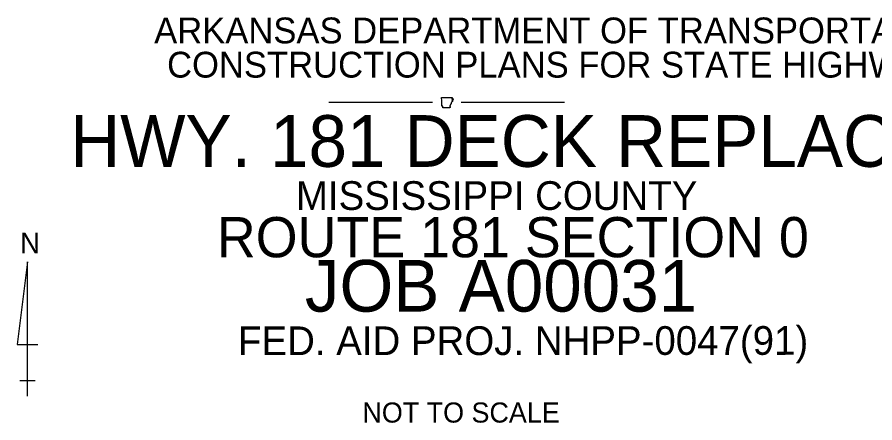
# Model space of a CAD drawing. Extents: x 2520745 to 2582119, y -1491628 to -1461664.
# Drawn here: x 2533060 to 2555441, y -1472350 to -1461753 of the extents above; entities that cross this region are included whole.
import ezdxf

# ---------------------------------------------------------------- set-up
doc = ezdxf.new("R2010")
doc.units = 0
doc.layers.add('2', color=7, linetype='Continuous')
doc.layers.add('R_Draft', color=7, linetype='Continuous')

msp = doc.modelspace()

# ---------------------------------------------------------------- linework, layer by layer
at = {"layer": 'R_Draft'}
for p, q in [((2541196.5562201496, -1463975.9826834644), (2543896.5562205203, -1463975.9826834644)), ((2544646.5562201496, -1463975.9826834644), (2547346.5562205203, -1463975.9826834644)), ((2533329.603670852, -1468144.847094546), (2533059.603670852, -1470304.847094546)), ((2533329.603670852, -1471654.8470944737), (2533329.603670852, -1468144.847094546)), ((2533059.603670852, -1470304.847094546), (2533599.603670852, -1470304.847094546)), ((2533125.853670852, -1471244.8470944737), (2533530.853670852, -1471244.8470944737))]:
    msp.add_line(p, q, dxfattribs=at)
for points in [[(2544131.813700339, -1463851.2283421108), (2544213.6743253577, -1463851.2789671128), (2544285.5112003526, -1463851.1270921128), (2544370.2574503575, -1463849.8108421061), (2544409.5424503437, -1463848.8995921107)], [(2544137.7368253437, -1464072.7127171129), (2544142.2930753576, -1463935.3670921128), (2544131.813700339, -1463851.2283421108)], [(2544397.3924503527, -1463888.4377171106), (2544435.8168253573, -1463886.4633421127)], [(2544351.374325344, -1464122.1227171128), (2544165.8337003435, -1464121.8189671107), (2544165.7324503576, -1464080.8633421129)]]:
    msp.add_lwpolyline(points, dxfattribs=at)
for points in [[(2544394.0005753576, -1463985.3845921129), (2544392.8362003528, -1463986.8527171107), (2544391.1149503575, -1463985.9414671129), (2544391.1149503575, -1463984.7264671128), (2544391.3680753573, -1463983.460842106), (2544390.7605753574, -1463982.6508421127), (2544389.6974503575, -1463983.0052171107), (2544389.6974503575, -1463984.5745921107), (2544389.5962003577, -1463986.0933421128), (2544389.2924503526, -1463988.2702171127), (2544390.001200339, -1463988.9283421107), (2544391.6212003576, -1463989.1308421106), (2544392.785575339, -1463989.4345921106), (2544393.4943253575, -1463990.5989671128), (2544393.4437003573, -1463992.0164671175), (2544392.8868253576, -1463993.3833421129), (2544392.0768253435, -1463994.497092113), (2544390.811200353, -1463994.9020921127), (2544389.7987003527, -1463994.2439671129), (2544389.393700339, -1463992.9277171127), (2544388.9380753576, -1463991.7633421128), (2544388.077450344, -1463990.9027171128), (2544387.1662003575, -1463991.8645921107), (2544386.9637003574, -1463993.6364671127), (2544387.0143253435, -1463995.1552171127), (2544387.0143253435, -1463997.2308421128), (2544388.3305753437, -1463998.5977171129), (2544389.140575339, -1464000.1670921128), (2544388.887450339, -1464001.5845921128), (2544387.925575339, -1464003.2552171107), (2544387.5205753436, -1464004.7233421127), (2544387.1155753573, -1464006.6977171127), (2544387.1662003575, -1464008.8745921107), (2544386.811825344, -1464011.0008421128), (2544386.103075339, -1464012.4183421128), (2544384.7868253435, -1464013.5827171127), (2544383.926200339, -1464014.3420921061), (2544383.217450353, -1464015.1014671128), (2544382.863075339, -1464016.620217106), (2544382.609950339, -1464017.6833421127), (2544381.6480753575, -1464018.9489671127), (2544380.888700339, -1464019.0502171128), (2544380.281200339, -1464018.5439671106), (2544380.0787003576, -1464017.6833421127), (2544380.0787003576, -1464016.8227171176), (2544379.6737003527, -1464015.9620921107), (2544378.408075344, -1464015.6077171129), (2544377.3955753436, -1464015.6583421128), (2544376.9399503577, -1464016.3670921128), (2544377.5980753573, -1464018.3414671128), (2544377.8512003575, -1464019.6070921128), (2544377.496825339, -1464021.3283421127), (2544377.6993253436, -1464021.5308421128), (2544375.876825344, -1464022.4927171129), (2544374.4087003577, -1464022.6445921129), (2544373.1937003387, -1464022.9989671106), (2544372.029325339, -1464023.7583421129), (2544371.4724503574, -1464024.8720921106), (2544370.6624503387, -1464025.7833421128), (2544369.953700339, -1464026.6439671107), (2544368.9918253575, -1464027.0489671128), (2544367.9287003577, -1464026.8464671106), (2544366.5112003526, -1464026.694592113), (2544365.701200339, -1464027.7070921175), (2544365.954325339, -1464029.1752171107), (2544366.9162003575, -1464030.0358421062), (2544368.3337003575, -1464030.4408421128), (2544369.8018253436, -1464030.3395921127), (2544371.2193253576, -1464030.1877171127), (2544372.5355753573, -1464030.8964671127), (2544372.282450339, -1464032.2633421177), (2544371.0168253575, -1464032.9214671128), (2544369.1437003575, -1464033.1239671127), (2544367.6249503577, -1464032.9720921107), (2544365.8024503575, -1464033.3770921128), (2544364.891200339, -1464034.5414671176), (2544365.397450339, -1464036.3133421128), (2544367.3718253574, -1464037.0220921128), (2544368.283075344, -1464038.6927171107), (2544368.3337003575, -1464040.2620921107), (2544367.6755753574, -1464042.3377171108), (2544366.7643253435, -1464043.2995921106), (2544364.9924503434, -1464043.7045921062), (2544363.625575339, -1464043.9577171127), (2544363.423075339, -1464046.2864671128), (2544362.815575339, -1464047.4508421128), (2544361.7524503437, -1464047.8052171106), (2544360.233700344, -1464047.0458421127), (2544359.3224503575, -1464046.6914671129), (2544358.2087003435, -1464046.1852171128), (2544356.791200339, -1464045.3245921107), (2544355.7280753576, -1464045.476467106), (2544356.031825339, -1464047.7039671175), (2544356.1330753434, -1464047.8052171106), (2544357.348075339, -1464049.475842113), (2544358.5630753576, -1464050.7920921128), (2544359.1199503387, -1464052.3614671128)], [(2544415.971825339, -1463935.2152171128), (2544416.1743253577, -1463936.6833421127), (2544415.3137003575, -1463938.2527171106), (2544415.009950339, -1463939.8220921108), (2544415.1618253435, -1463941.3914671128), (2544413.5418253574, -1463942.2520921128), (2544412.1243253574, -1463943.2645921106), (2544412.934325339, -1463944.4795921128), (2544414.4530753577, -1463945.5933421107), (2544415.971825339, -1463946.4539671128), (2544416.9337003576, -1463947.3145921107), (2544417.1868253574, -1463949.3902171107), (2544417.4399503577, -1463950.7064671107), (2544417.9462003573, -1463952.5289671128), (2544418.1487003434, -1463953.7945921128), (2544417.237450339, -1463955.3133421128), (2544416.1743253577, -1463955.6170921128), (2544415.0605753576, -1463955.2627171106), (2544413.7443253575, -1463955.1614671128), (2544412.681200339, -1463956.1739671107), (2544411.9218253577, -1463957.5914671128), (2544411.1624503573, -1463959.0089671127), (2544410.6055753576, -1463960.2239671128), (2544410.0487003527, -1463961.5402171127), (2544408.9349503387, -1463963.0589671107), (2544407.5680753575, -1463963.3120921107), (2544405.9480753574, -1463963.7170921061), (2544404.986200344, -1463964.8308421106), (2544405.1380753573, -1463966.7039671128), (2544406.0493253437, -1463967.9695921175), (2544406.7580753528, -1463969.5389671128), (2544407.264325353, -1463970.9058421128), (2544407.0112003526, -1463972.6270921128), (2544406.3024503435, -1463973.8927171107), (2544405.391200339, -1463974.6520921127), (2544404.986200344, -1463976.2720921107), (2544404.328075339, -1463977.487092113), (2544403.720575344, -1463977.892092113), (2544402.5055753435, -1463977.7908421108), (2544401.1893253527, -1463977.5377171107), (2544400.0755753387, -1463977.6389671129), (2544399.012450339, -1463978.1958421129), (2544397.9493253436, -1463977.8414671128), (2544396.8355753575, -1463976.6264671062), (2544395.9243253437, -1463975.7152171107), (2544394.9118253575, -1463975.360842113), (2544393.8487003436, -1463975.9177171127), (2544393.6462003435, -1463977.5883421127), (2544394.1524503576, -1463979.309592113), (2544394.6080753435, -1463981.6383421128), (2544394.1524503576, -1463983.0558421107), (2544394.0005753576, -1463985.3845921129)], [(2544409.5424503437, -1463848.8995921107), (2544409.7955753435, -1463851.1270921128), (2544410.504325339, -1463852.2914671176), (2544410.6055753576, -1463854.4177171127), (2544411.4662003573, -1463855.3289671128), (2544412.934325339, -1463856.2402171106), (2544414.2505753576, -1463857.7083421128), (2544414.5543253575, -1463859.4295921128), (2544414.149325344, -1463861.2014671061), (2544414.0480753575, -1463863.1758421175), (2544413.845575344, -1463864.8970921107), (2544413.5418253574, -1463866.4664671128), (2544412.3268253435, -1463867.7320921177), (2544411.1624503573, -1463868.643342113), (2544410.0993253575, -1463869.7064671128), (2544409.3399503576, -1463870.8202171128), (2544408.0237003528, -1463872.0352171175), (2544406.7074503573, -1463873.3008421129), (2544405.644325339, -1463874.4145921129), (2544404.5812003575, -1463875.8320921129), (2544404.074950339, -1463877.4014671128), (2544402.910575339, -1463878.5152171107), (2544401.999325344, -1463879.5277171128), (2544400.7843253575, -1463880.8945921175), (2544400.1768253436, -1463882.2614671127), (2544399.012450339, -1463883.830842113), (2544398.759325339, -1463885.3495921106), (2544397.999950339, -1463886.5645921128), (2544397.9493253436, -1463886.767092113)], [(2544435.259950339, -1463886.5139671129), (2544435.8168253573, -1463886.4633421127), (2544437.5380753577, -1463888.2858421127), (2544438.2974503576, -1463889.804592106), (2544439.4112003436, -1463890.6652171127), (2544440.6768253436, -1463891.1208421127), (2544441.6387003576, -1463892.2852171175), (2544442.296825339, -1463893.5508421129), (2544441.942450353, -1463894.6645921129), (2544440.5249503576, -1463894.7658421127), (2544438.9555753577, -1463895.0189671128), (2544437.436825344, -1463894.9683421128), (2544436.2218253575, -1463895.9808421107), (2544437.335575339, -1463897.3477171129), (2544438.8037003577, -1463898.6133421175), (2544439.2087003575, -1463899.9802171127), (2544438.3987003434, -1463901.2964671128), (2544436.7787003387, -1463902.0052171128), (2544435.2093253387, -1463902.6127171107), (2544433.7918253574, -1463903.8277171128), (2544433.133700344, -1463904.9920921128), (2544431.564325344, -1463905.4983421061), (2544429.9443253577, -1463905.9539671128), (2544428.5268253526, -1463906.1058421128), (2544426.906825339, -1463906.4095921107), (2544425.337450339, -1463907.1689671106), (2544424.6793253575, -1463908.4852171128), (2544424.8818253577, -1463910.3583421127), (2544424.831200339, -1463912.3327171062), (2544426.5018253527, -1463912.9908421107), (2544427.969950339, -1463913.0414671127), (2544429.3874503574, -1463913.8008421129), (2544429.235575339, -1463914.9145921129), (2544428.172450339, -1463916.3320921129), (2544426.906825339, -1463917.4458421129), (2544425.641200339, -1463918.0027171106), (2544424.4768253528, -1463919.0658421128), (2544424.8818253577, -1463920.1289671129), (2544425.9449503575, -1463920.8377171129), (2544426.7043253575, -1463922.0020921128), (2544426.603075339, -1463923.0652171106), (2544425.3880753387, -1463923.8245921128), (2544424.071825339, -1463923.5208421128), (2544423.1099503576, -1463922.2552171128), (2544421.9962003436, -1463921.8502171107), (2544421.0343253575, -1463921.3945921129), (2544419.920575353, -1463922.0527171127), (2544419.920575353, -1463923.5208421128), (2544419.5155753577, -1463925.0902171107), (2544419.8699503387, -1463926.2545921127), (2544420.3255753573, -1463927.8745921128), (2544420.2749503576, -1463929.0895921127), (2544419.8699503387, -1463930.8108421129), (2544419.0093253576, -1463932.5827171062), (2544417.9968253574, -1463933.1395921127), (2544417.5918253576, -1463931.2158421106), (2544417.389325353, -1463929.6464671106), (2544416.781825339, -1463928.7352171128), (2544415.971825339, -1463928.6845921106), (2544414.9087003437, -1463929.4439671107), (2544413.7443253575, -1463930.6083421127), (2544412.2762003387, -1463931.8739671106), (2544411.4155753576, -1463933.1395921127), (2544411.8712003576, -1463934.7089671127), (2544412.9849503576, -1463935.1139671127), (2544413.845575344, -1463934.8102171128), (2544414.3012003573, -1463933.7977171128), (2544415.1618253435, -1463933.6458421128), (2544415.971825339, -1463935.2152171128)], [(2544165.7324503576, -1464080.8633421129), (2544165.9349503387, -1464080.9645921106), (2544164.9730753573, -1464080.3064671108), (2544163.6568253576, -1464079.6483421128), (2544162.188700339, -1464079.5470921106), (2544160.3155753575, -1464079.293967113), (2544158.7462003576, -1464079.1420921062), (2544157.1262003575, -1464078.0789671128), (2544155.4049503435, -1464079.1927171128), (2544153.4812003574, -1464080.0027171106), (2544152.3674503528, -1464079.0914671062), (2544150.8993253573, -1464079.6989671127), (2544149.8868253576, -1464079.3952171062), (2544148.1149503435, -1464080.6102171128), (2544146.4443253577, -1464080.1545921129), (2544145.2293253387, -1464080.5089671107), (2544143.710575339, -1464080.4583421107), (2544143.406825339, -1464078.7370921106), (2544141.9387003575, -1464078.4839671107), (2544140.673075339, -1464077.7752171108), (2544139.812450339, -1464076.0033421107), (2544139.2049503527, -1464074.6364671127), (2544137.7368253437, -1464072.7127171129)], [(2544359.1199503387, -1464052.3614671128), (2544358.613700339, -1464053.5258421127), (2544358.0568253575, -1464055.5508421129), (2544358.2087003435, -1464057.2720921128), (2544358.9680753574, -1464058.7402171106), (2544360.1830753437, -1464059.5502171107), (2544361.499325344, -1464060.7145921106), (2544361.3980753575, -1464062.4864671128), (2544360.6387003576, -1464063.1445921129), (2544358.866825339, -1464062.688967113), (2544357.4999503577, -1464062.0814671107), (2544356.335575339, -1464062.4358421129), (2544354.766200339, -1464063.195217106), (2544353.6018253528, -1464063.3470921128), (2544353.6524503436, -1464065.7770921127), (2544355.221825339, -1464067.4983421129), (2544356.5887003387, -1464067.4983421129), (2544358.158075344, -1464067.7008421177), (2544358.7149503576, -1464069.5233421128), (2544357.8037003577, -1464071.0420921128), (2544356.284950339, -1464071.8014671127), (2544354.3612003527, -1464070.8902171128), (2544352.9943253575, -1464069.9283421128), (2544351.6274503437, -1464069.017092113), (2544349.9062003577, -1464068.5614671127), (2544348.9443253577, -1464068.7639671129), (2544348.488700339, -1464070.8902171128), (2544349.298700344, -1464072.813967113), (2544350.6149503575, -1464074.1302171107), (2544351.829950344, -1464075.8514671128), (2544351.6274503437, -1464077.117092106), (2544350.7162003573, -1464077.471467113), (2544349.0962003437, -1464077.8258421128), (2544348.1343253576, -1464078.3320921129), (2544347.8812003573, -1464078.7370921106), (2544348.3874503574, -1464080.4583421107), (2544348.843075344, -1464082.3314671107), (2544348.843075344, -1464083.7489671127), (2544348.286200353, -1464085.0652171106), (2544347.425575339, -1464087.0902171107), (2544347.5268253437, -1464088.4064671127), (2544348.1343253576, -1464089.0139671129), (2544348.8937003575, -1464088.8114671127), (2544349.9062003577, -1464088.1027171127), (2544350.564325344, -1464087.2927171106), (2544351.1212003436, -1464086.2802171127), (2544352.1843253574, -1464085.4195921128), (2544353.5005753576, -1464086.178967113), (2544353.8043253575, -1464087.7483421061), (2544353.0449503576, -1464089.1152171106), (2544351.9818253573, -1464089.7227171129), (2544350.665575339, -1464090.2289671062), (2544349.7037003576, -1464091.3427171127), (2544349.9568253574, -1464092.658967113), (2544350.7162003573, -1464093.3677171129), (2544352.5893253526, -1464093.0133421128), (2544353.8549503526, -1464092.4564671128), (2544354.563700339, -1464091.7477171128), (2544355.4243253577, -1464090.8870921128), (2544355.8799503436, -1464090.026467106), (2544356.538075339, -1464089.1152171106), (2544357.702450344, -1464088.8620921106), (2544358.2593253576, -1464089.6214671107), (2544358.0568253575, -1464091.3427171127), (2544357.348075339, -1464092.9627171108), (2544356.3862003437, -1464094.3295921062), (2544355.3230753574, -1464095.2914671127), (2544354.0068253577, -1464097.3670921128), (2544354.2599503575, -1464099.2908421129), (2544354.766200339, -1464100.8602171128), (2544355.4749503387, -1464102.0752171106), (2544356.6899503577, -1464101.8220921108), (2544358.0568253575, -1464101.6702171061), (2544358.866825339, -1464102.3283421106), (2544358.7655753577, -1464103.7458421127), (2544357.7530753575, -1464105.1127171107), (2544356.791200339, -1464106.428967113), (2544356.284950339, -1464108.2514671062), (2544356.4874503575, -1464109.517092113), (2544356.4874503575, -1464110.6814671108), (2544356.082450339, -1464111.9470921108), (2544355.373700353, -1464112.6558421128), (2544353.5005753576, -1464112.6052171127), (2544351.5262003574, -1464112.4027171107), (2544350.4630753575, -1464113.0102171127), (2544350.665575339, -1464114.731467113), (2544351.829950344, -1464115.9970921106), (2544352.639950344, -1464116.6552171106), (2544353.8043253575, -1464118.0727171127), (2544354.310575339, -1464119.237092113), (2544354.1587003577, -1464120.2495921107), (2544353.449950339, -1464121.1102171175), (2544351.374325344, -1464122.1227171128)]]:
    msp.add_spline(points, degree=3, dxfattribs=at)

# ---------------------------------------------------------------- texts
at = {"layer": '2'}
msp.add_text('FED. AID PROJ. NHPP-0047(91)', height=749.9972494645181, rotation=0.03493681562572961, dxfattribs=at).set_placement((2538822.662184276, -1470581.9473962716))
at = {"layer": 'R_Draft'}
for s, height, p in [('ARKANSAS DEPARTMENT OF TRANSPORTATION', 674.9999999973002, (2536635.2127163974, -1462438.482683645)), ('CONSTRUCTION PLANS FOR STATE HIGHWAY', 674.9999999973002, (2536971.605432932, -1463332.482683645)), ('HWY. 181 DECK REPLACEMENT', 1350.0000000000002, (2534444.1940156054, -1465663.4826834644)), ('MISSISSIPPI COUNTY', 750, (2540333.76094474, -1466788.4826834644)), ('ROUTE 181 SECTION 0', 1050, (2538270.375117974, -1468025.0999185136)), ('N', 539.99999999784, (2533134.6036705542, -1467919.847094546)), ('JOB A00031', 1350.0000000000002, (2540568.2097636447, -1469444.9697688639)), ('NOT TO SCALE', 525, (2542069.173788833, -1472342.5168396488))]:
    msp.add_text(s, height=height, dxfattribs=at).set_placement(p)

doc.saveas('drawing.dxf')
